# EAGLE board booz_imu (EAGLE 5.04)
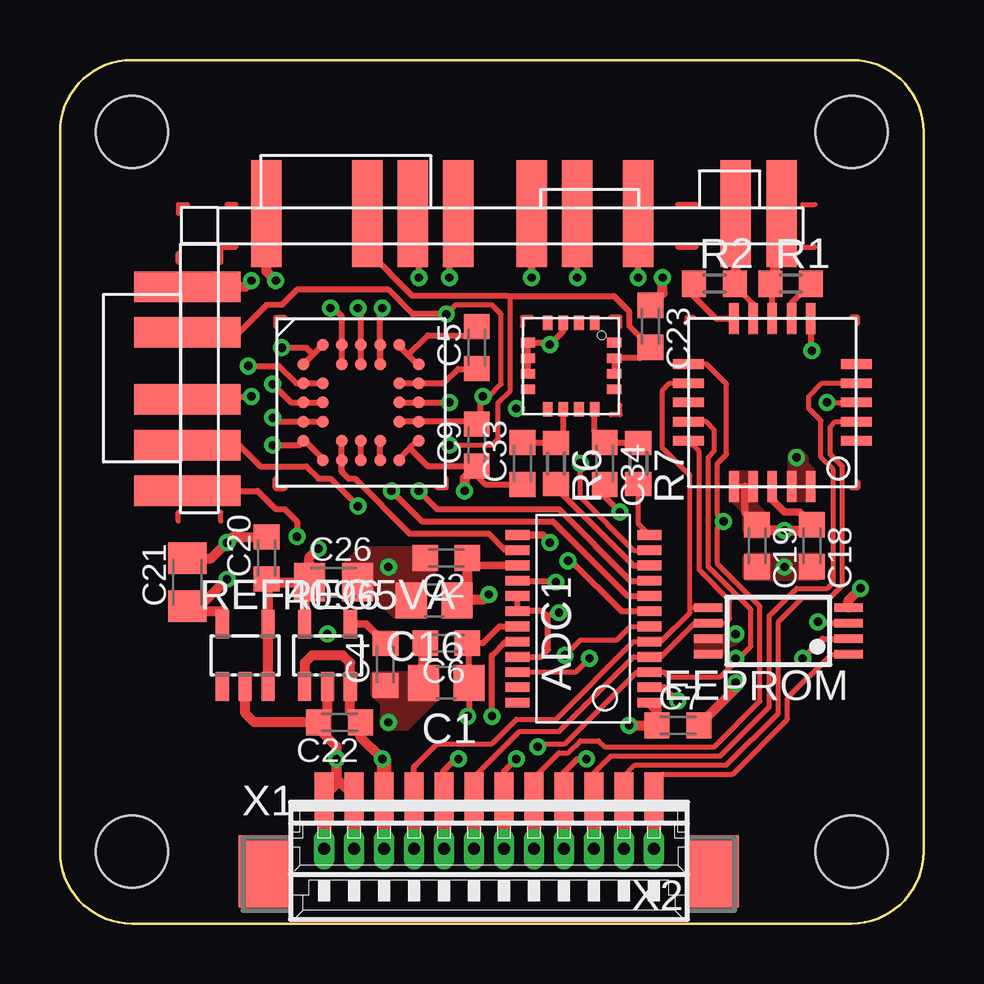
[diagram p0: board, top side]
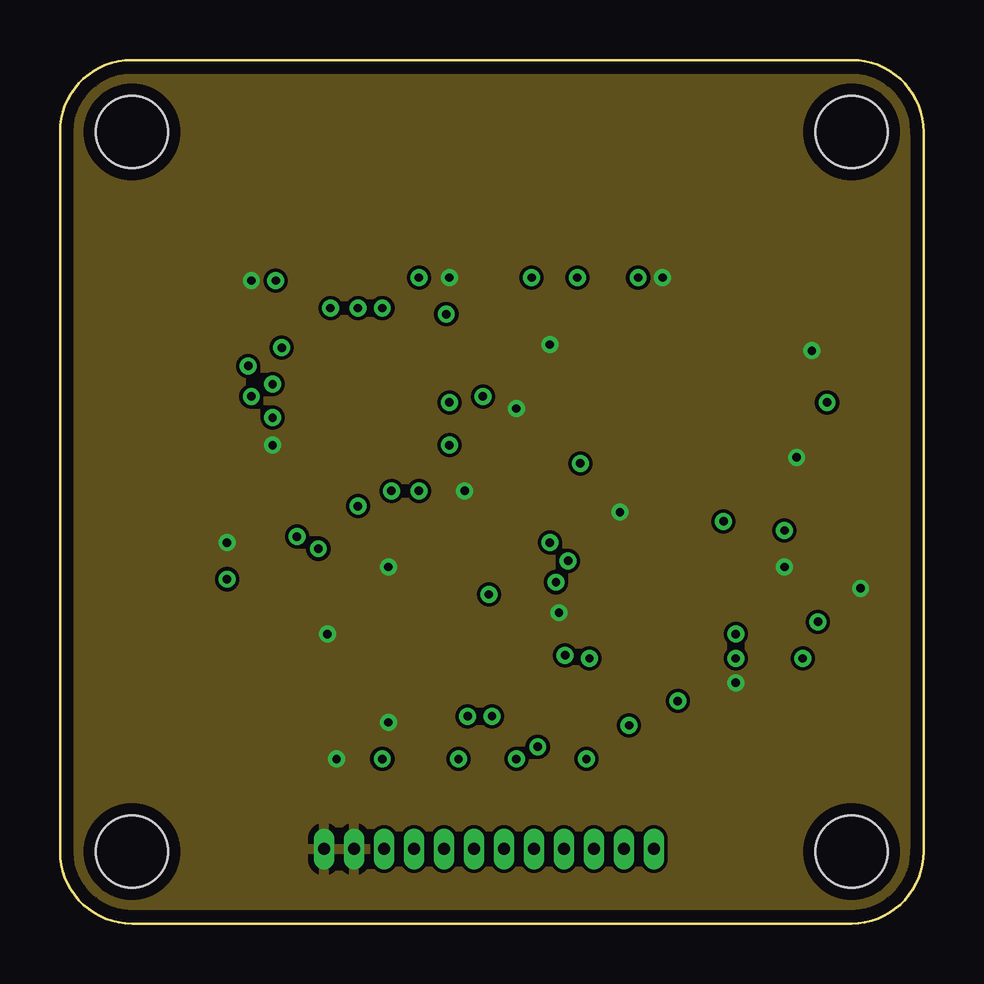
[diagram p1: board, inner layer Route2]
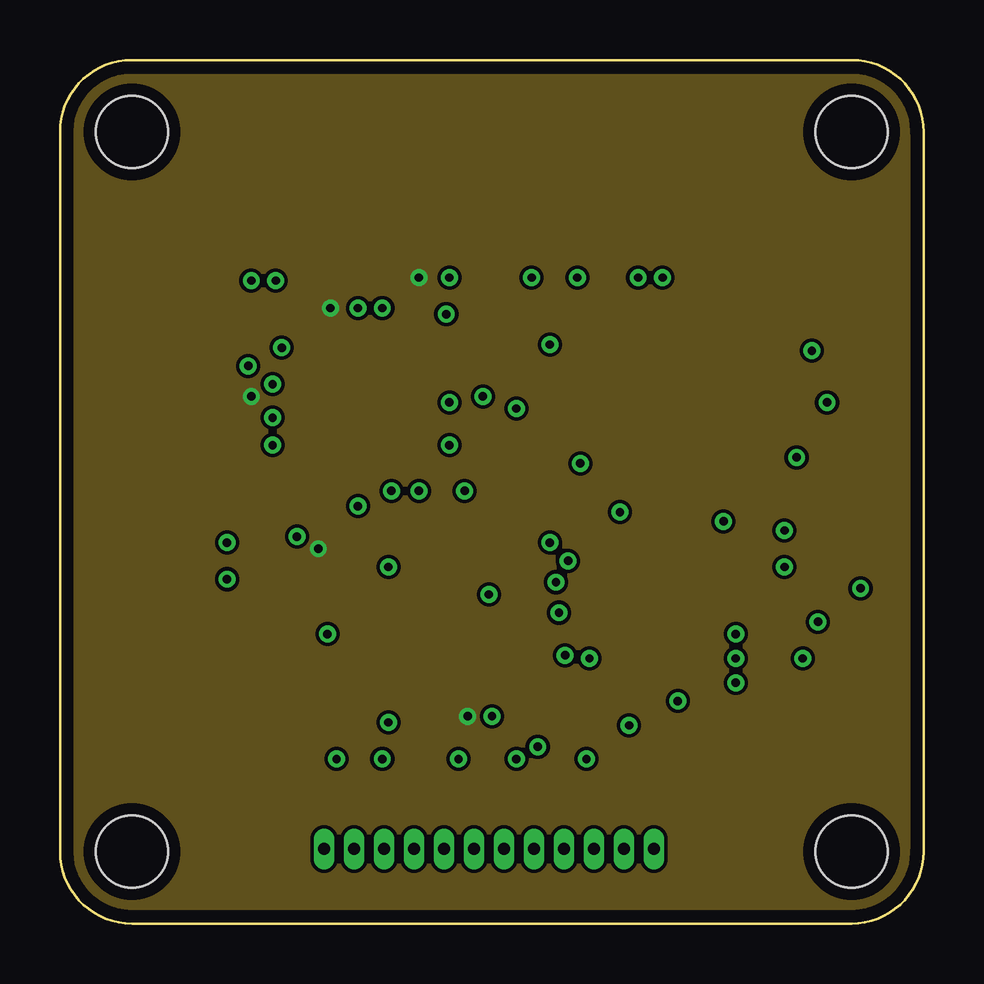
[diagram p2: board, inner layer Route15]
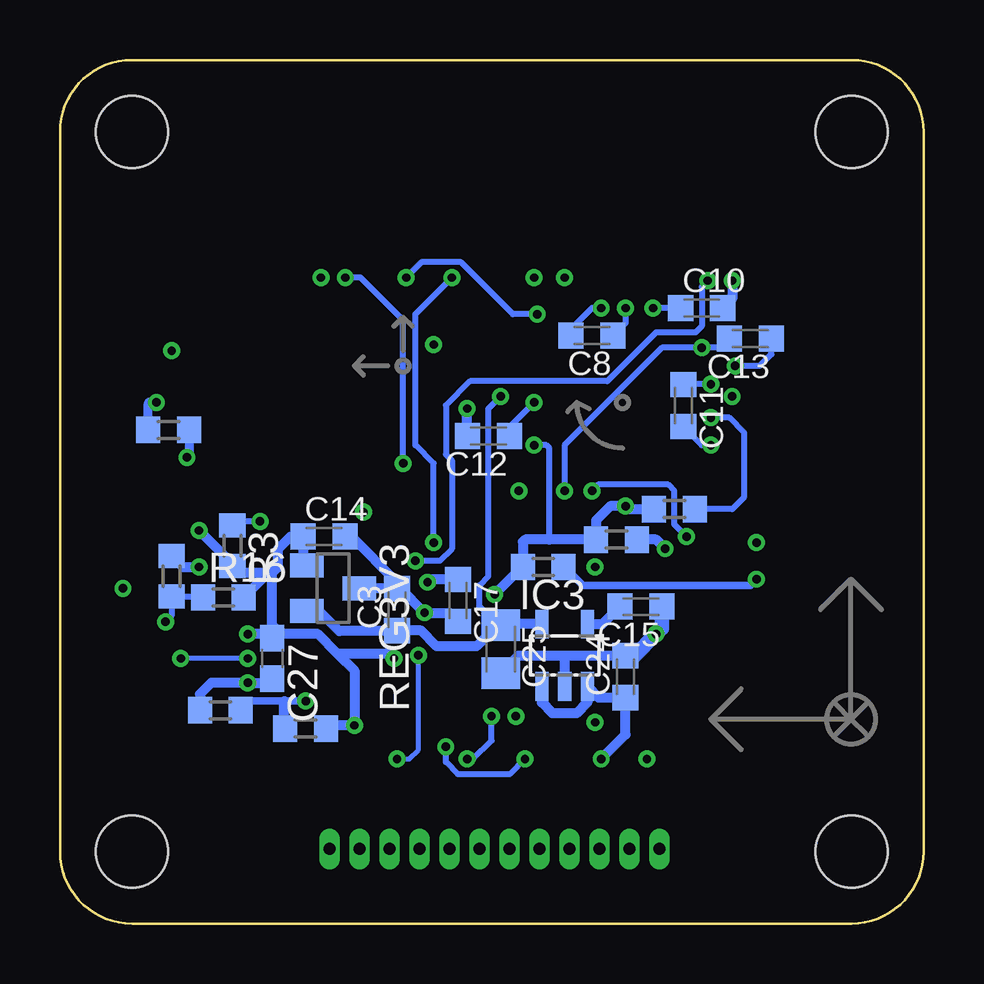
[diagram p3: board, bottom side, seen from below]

Size 36 x 36 mm. Coordinates in mm from the lower left corner, seen from the top.
Outline: 3,36 33,36 arc-90 36,33 36,3 arc-90 33,0 3,0 arc-90 0,3 0,33 arc-90 3,36
Copper layers (1*2+15*16): Top 0.035mm / dielectric 0.2mm / Route2 0.035mm / dielectric 1.5mm / Route15 0.035mm / dielectric 0.2mm / Bottom 0.035mm
Design rules "eurocircuits_verified_4l": minimum track width 0.15mm, minimum drill 0.35mm, track to track 0.15mm, track to pad 0.15mm, pad to pad 0.15mm, via to via 0.15mm, smd to smd 0.15mm, copper to edge 20mil, drill to drill 8mil, minimum pad ring 0.177mm, minimum via ring 0.177mm, stop-mask expansion 4mil, vias tented up to drill 14mil, thermal gap 10mil
Holes 3 mm at 3,33 33,33 33,3 3,3
tKeepout: area 0,30 to 6,36; area 30,30 to 36,36; area 0,0 to 6,6; area 30,0 to 36,6

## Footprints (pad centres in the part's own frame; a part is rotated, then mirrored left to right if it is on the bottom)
QSOP24 = smd 0.4 x 1: P$1 -3.493,-2.75; P$2 -2.857,-2.75; P$3 -2.223,-2.75; P$4 -1.587,-2.75; P$5 -0.953,-2.75; P$6 -0.318,-2.75; P$7 0.318,-2.75; P$8 0.953,-2.75; P$9 1.587,-2.75; P$10 2.223,-2.75; P$11 2.857,-2.75; P$12 3.493,-2.75; P$13 3.493,2.75; P$14 2.857,2.75; P$15 2.223,2.75; P$16 1.587,2.75; P$17 0.953,2.75; P$18 0.318,2.75; P$19 -0.318,2.75; P$20 -0.953,2.75; P$21 -1.587,2.75; P$22 -2.223,2.75; P$23 -2.857,2.75; P$24 -3.493,2.75
C0805 = smd 1.3 x 1.5: 1 -0.95,0; 2 0.95,0
C0603K = smd 1.05 x 1.08: 1 -0.875,0; 2 0.875,0
C0805K = smd 1.3 x 1.6: 1 -1,0; 2 1,0
C0603 = smd 1.1 x 1: 1 -0.85,0; 2 0.85,0
TSSOP8 = smd 0.35 x 1.2: 1 -0.975,-2.925; 2 -0.325,-2.925; 3 0.325,-2.925; 4 0.975,-2.925; 5 0.975,2.925; 6 0.325,2.925; 7 -0.325,2.925; 8 -0.975,2.925
BC-32 = smd 0.5 x 0.5: A2 -1.6,2.4; A3 -0.8,2.4; A4 0,2.4; A5 0.8,2.4; A6 1.6,2.4; B1 -2.4,1.6; B3 -0.8,1.6; B4 0,1.6; B5 0.8,1.6; B7 2.4,1.6; C1 -2.4,0.8; C2 -1.6,0.8; C6 1.6,0.8; C7 2.4,0.8; D1 -2.4,0; D2 -1.6,0; D6 1.6,0; D7 2.4,0; E1 -2.4,-0.8; E2 -1.6,-0.8; E6 1.6,-0.8; E7 2.4,-0.8; F1 -2.4,-1.6; F3 -0.8,-1.6; F4 0,-1.6; F5 0.8,-1.6; F7 2.4,-1.6; G2 -1.6,-2.4; G3 -0.8,-2.4; G4 0,-2.4; G5 0.8,-2.4; G6 1.6,-2.4
SOT23-5 = smd 0.55 x 1.2: 1 -0.95,-1.3; 2 0,-1.3; 3 0.95,-1.3; 4 0.95,1.3; 5 -0.95,1.3
QFN20 = smd 1.3 x 0.4: P$1 -3.5,1.6; P$2 -3.5,0.8; P$3 -3.5,0; P$4 -3.5,-0.8; P$5 -3.5,-1.6; P$11 3.5,-1.6; P$12 3.5,-0.8; P$13 3.5,0; P$14 3.5,0.8; P$15 3.5,1.6 | smd 0.4 x 1.3: P$6 -1.6,-3.5; P$7 -0.8,-3.5; P$8 0,-3.5; P$9 0.8,-3.5; P$10 1.6,-3.5; P$16 1.6,3.5; P$17 0.8,3.5; P$18 0,3.5; P$19 -0.8,3.5; P$20 -1.6,3.5
R0603 = smd 1 x 1.1: 1 -0.85,0; 2 0.85,0
SOT23-5L = smd 0.55 x 1.2: 1 -0.95,-1.3; 2 0,-1.3; 3 0.95,-1.3; 4 0.95,1.3; 5 -0.95,1.3
SOT23 = smd 1 x 1.4: 1 -0.95,-1.1; 2 0.95,-1.1; 3 0,1.1
LSCFP = smd 0.6 x 0.4: P$1 -1.8,0.975; P$2 -1.8,0.325; P$3 -1.8,-0.325; P$4 -1.8,-0.975; P$9 1.8,-0.975; P$10 1.8,-0.325; P$11 1.8,0.325; P$12 1.8,0.975 | smd 0.4 x 0.6: P$5 -0.975,-1.8; P$6 -0.325,-1.8; P$7 0.325,-1.8; P$8 0.975,-1.8; P$13 0.975,1.8; P$14 0.325,1.8; P$15 -0.325,1.8; P$16 -0.975,1.8
53261-12 = smd 0.8 x 2: 1 6.875,-2.5; 2 5.625,-2.5; 3 4.375,-2.5; 4 3.125,-2.5; 5 1.875,-2.5; 6 0.625,-2.5; 7 -0.625,-2.5; 8 -1.875,-2.5; 9 -3.125,-2.5; 10 -4.375,-2.5; 11 -5.625,-2.5; 12 -6.875,-2.5 | smd 2.1 x 3: S1 9.375,0.625; S2 -9.375,0.625
53047-12 = drill 0.5 pad 0.698 long: 1 6.875,0.45; 2 5.625,0.45; 3 4.375,0.45; 4 3.125,0.45; 5 1.875,0.45; 6 0.625,0.45; 7 -0.625,0.45; 8 -1.875,0.45; 9 -3.125,0.45; 10 -4.375,0.45; 11 -5.625,0.45; 12 -6.875,0.45
IMU_XZ = smd 1.27 x 4.445: GND 3.81,0.508; RATE -4.699,0.508; VDDA -0.889,0.508; VDDD 1.905,0.508; VREF -2.794,0.508
IMU_YZ_MAG = smd 1.27 x 4.445: ACCEL_H 3.81,0.508; ACCEL_V 8.255,0.508; GND 0.762,0.508; MAG_N 12.319,0.508; MAG_P 14.224,0.508; RATE_X -7.239,0.508; VDDA -1.143,0.508; VDDD 5.715,0.508; VREF -3.048,0.508

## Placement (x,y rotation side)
ADC1  MAX1168  [QSOP24]  21.82,12.7 90 top
C1  4.7uF  [C0805]  16.11,10.04 180 top
C2  100nF  [C0603K]  16.11,15.24 180 top
C3  100nF  [C0603K]  21.95,13.09 90 bottom
C4  10nF  [C0603K]  13.56,10.8 90 top
C5  22nF  [C0603K]  17.38,24.01 90 top
C6  100nF  [C0603K]  16.11,11.69 180 top
C7  100nF  [C0603K]  25.76,8.26 0 top
C8  22nF  [C0603K]  13.82,24.52 180 bottom
C9  100nF  [C0603K]  17.38,19.94 90 top
C10  100nF  [C0603K]  9.25,25.66 0 bottom
C11  100nF  [C0603K]  10.01,21.59 270 bottom
C12  47nF  [C0603K]  18.14,20.32 180 bottom
C13  22nF  [C0603K]  7.22,24.39 180 bottom
C14  100nF  [C0603K]  25,16.13 0 bottom
C15  10nF  [C0603K]  11.79,13.21 180 bottom
C16  4.7uF  [C0805]  15.6,13.47 180 top
C17  100nF  [C0603K]  19.41,13.47 270 bottom
C18  100nF  [C0603K]  31.34,15.75 270 top
C19  100nF  [C0603K]  29.06,15.75 270 top
C20  100nF  [C0603K]  8.61,15.24 90 top
C21  4.7uF/Low ESR  [C0805K]  5.31,14.23 90 top
C22  2.2uF/Low ESR  [C0603K]  11.66,8.39 180 top
C23  100nF  [C0603K]  24.61,24.9 270 top
C24  2.2uF/Low ESR  [C0603K]  12.42,10.29 90 bottom
C25  4.7uF/10V/Low ESR  [C0805K]  17.63,11.43 270 bottom
C26  4.7uF/10V/Low ESR  [C0805K]  11.41,14.23 0 top
C27  100nF  [C0603]  27.15,11.05 270 bottom
C33  100nF  [C0603K]  19.28,19.18 90 top
C34  100nF  [C0603K]  22.71,19.18 270 top
EEPROM  25LC040ST  [TSSOP8]  29.95,12.2 90 top
GYRO_Z  ADXR  [BC-32]  12.55,21.72 0 top
IC3  LP2992  [SOT23-5]  14.96,11.18 0 bottom
MAG  MS2100  [QFN20]  29.69,21.72 180 top
R1  43R  [R0603]  30.46,26.67 0 top
R2  43R  [R0603]  27.28,26.67 0 top
R3  10k  [R0603]  28.81,15.75 270 bottom
R4  39k/DNP  [R0603]  31.47,20.58 180 bottom
R5  10k/DNP  [R0603]  25.76,8.13 0 bottom
R6  12k  [R0603]  20.68,19.18 270 top
R7  12k  [R0603]  24.11,19.18 270 top
R8  0/DNP  [R0603]  12.8,16.01 180 bottom
R9  0/DNP  [R0603]  15.85,14.86 180 bottom
R10  0/DNP  [R0603]  10.39,17.28 0 bottom
R11  10k/DNP  [R0603]  29.31,8.89 0 bottom
R15  0/DNP  [R0603]  31.34,14.48 270 bottom
R16  4k7  [R0603]  29.19,13.59 0 bottom
REF4096  LM4132  [SOT23-5L]  7.72,11.18 0 top
REG3V3  LM3480  [SOT23]  24.61,13.97 270 bottom
REG5VA  LP2992  [SOT23-5]  11.15,11.18 0 top
U$2  ADXL320  [LSCFP]  21.31,23.24 270 top
X1  53261-12  [53261-12]  17.88,2.8 180 top
X2  53047-12  [53047-12]  17.88,3.56 180 top
XZ_BOARD  IMU_XZ_2  [IMU_XZ]  5.82,22.74 90 top
YZ_BOARD  IMU_YZ_MAG_2  [IMU_YZ_MAG]  15.85,29.09 0 top

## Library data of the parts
ADC1 MAG REF4096 REG3V3 XZ_BOARD YZ_BOARD = booz
C1-C27 C33 C34 R1-R11 R15 R16 = rcl
EEPROM = microchip
GYRO_Z U$2 = paparazzi
IC3 REG5VA = v-reg-micrel
X1 X2 = con-molex

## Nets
+3V3: ADC1.P$1 ADC1.P$22 C7.1 C14.1 C18.1 C19.1 C27.1 EEPROM.7 EEPROM.8 MAG.P$16 MAG.P$17 MAG.P$18 R3.2 R5.2 R16.2 REG3V3.1
+5V: C3.1 C9.2 C25.1 GYRO_Z.E6 GYRO_Z.E7 IC3.5 REG3V3.2 XZ_BOARD.VDDD YZ_BOARD.VDDD
+5VA: ADC1.P$19 C1.1 C6.1 C10.1 C20.1 C26.1 GYRO_Z.A3 GYRO_Z.B3 R8.1 REF4096.3 REF4096.4 REG5VA.5 XZ_BOARD.VDDA YZ_BOARD.VDDA
+6V5: C22.1 C24.1 IC3.1 IC3.3 REG5VA.1 REG5VA.3 X1.3 X2.3
ACCEL_X: ADC1.P$12 R7.2
ACCEL_X2: ADC1.P$13 YZ_BOARD.ACCEL_H
ACCEL_Y: ADC1.P$10 R6.2
ACCEL_Z: ADC1.P$11 YZ_BOARD.ACCEL_V
ADC_CS: ADC1.P$20 X1.7 X2.7
ADC_EOC: ADC1.P$6 X1.9 X2.9
EEPROM_CS: EEPROM.1 X1.12 X2.12
GND: ADC1.P$17 ADC1.P$18 ADC1.P$21 C1.2 C2.2 C3.2 C4.1 C6.2 C7.2 C9.1 C10.2 C11.2 C12.2 C14.2 C15.1 C16.2 C17.2 C18.2 C19.2 C20.2 C21.2 C22.2 C23.1 C24.2 C25.2 C26.2 C27.2 C33.1 C34.2 EEPROM.4 GYRO_Z.F1 GYRO_Z.F7 GYRO_Z.G2 GYRO_Z.G6 IC3.2 MAG.P$6 MAG.P$19 MAG.P$20 R4.1 R11.1 R15.1 REF4096.2 REG3V3.3 REG5VA.2 U$2.P$3 U$2.P$5 U$2.P$6 U$2.P$7 X1.1 X1.2 X2.1 X2.2 XZ_BOARD.GND YZ_BOARD.GND
MAG_CS: MAG.P$11 R3.1 X1.8 X2.8
MAG_DRDY: MAG.P$4 X1.10 X2.10
MAG_N: MAG.P$9 R2.2 YZ_BOARD.MAG_N
MAG_P: MAG.P$8 R1.1 YZ_BOARD.MAG_P
MAG_RESET: MAG.P$2 X1.11 X2.11
MISO: ADC1.P$3 EEPROM.2 MAG.P$14 X1.5 X2.5
MOSI: ADC1.P$5 EEPROM.5 MAG.P$12 X1.4 X2.4
N$1: ADC1.P$2 R5.1 R11.2
N$3: ADC1.P$16 C17.1
N$7: C5.2 GYRO_Z.A6 GYRO_Z.B7
N$8: C5.1 GYRO_Z.C6 GYRO_Z.C7
N$9: C8.2 GYRO_Z.A5 GYRO_Z.B5
N$10: C8.1 GYRO_Z.A4 GYRO_Z.B4
N$11: C13.1 GYRO_Z.C1 GYRO_Z.C2
N$12: C12.1 GYRO_Z.D6 GYRO_Z.D7
N$13: C11.1 GYRO_Z.D1 GYRO_Z.D2
N$15: MAG.P$10 R2.1
N$16: MAG.P$7 R1.2
N$18: MAG.P$3 R4.2
N$19: C15.2 IC3.4
N$20: C33.2 R6.1 U$2.P$10
N$23: C4.2 REG5VA.4
N$32: C34.1 R7.1 U$2.P$12
N$39: EEPROM.3 R15.2 R16.1
RATE_X: ADC1.P$8 XZ_BOARD.RATE
RATE_Y: ADC1.P$7 YZ_BOARD.RATE_X
RATE_Z: ADC1.P$9 C13.2 GYRO_Z.A2 GYRO_Z.B1
SCK: ADC1.P$4 EEPROM.6 MAG.P$15 X1.6 X2.6
ST1: GYRO_Z.F5 GYRO_Z.G5
ST2: GYRO_Z.F4 GYRO_Z.G4
TEMP: ADC1.P$14 GYRO_Z.F3 GYRO_Z.G3
V4096: C21.1 R9.1 REF4096.5
VRATIO_OR_2V5: GYRO_Z.E1 GYRO_Z.E2 R10.2
VREF: ADC1.P$15 C2.1 C16.1 C23.2 R8.2 R9.2 R10.1 U$2.P$14 U$2.P$15 XZ_BOARD.VREF YZ_BOARD.VREF

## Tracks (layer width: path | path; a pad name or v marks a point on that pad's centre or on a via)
+3V3  (via drill 0.35)
  Top 0.203: MAG.P$16 28.55,18.22 MAG.P$17 | ADC1.P$22 21.5,10.48 v22.07,11.05
  Top 0.305: MAG.P$18 29.69,17.66 30.2,17.15 30.82,17.15 C18.1 | 28.55,18.22 28.55,17.13 C19.1
  Top 0.406: ADC1.P$1 24.55,9.21 24.88,8.88 C7.1 v23.72,8.26 | C18.1 31.11,16.39 v30.2,16.39 29.3,16.39 C19.1
  Bottom 0.254: R5.2 24.61,8.13
  Bottom 0.406: C14.1 26.39,16.13 26.9,15.62 26.9,14.86 27.15,14.61 | C14.1 25.71,15.98 | 27.15,14.61 27.28,14.61 | REG3V3.1 25.87,15.08 C14.1 | v30.2,16.39 28.81,14.99 R3.2 28.51,14.61 27.28,14.61 | R16.2 27.32,14.61 27.28,14.61 | 27.15,12.45 C27.1 27.32,12.07 v28.17,12.07 | 27.15,12.45 27.15,14.61 | 27.15,12.45 26.77,12.07 25.25,12.07 24.42,11.24 | 24.42,11.24 23.72,10.55 v23.72,8.26 24.78,8.26 R5.2 | v22.07,11.05 22.26,11.24 24.42,11.24
  pour Top (no thermals): 26.52,11.94 26.52,11.18 27.53,11.18 28.42,11.94 28.42,12.2 28.17,12.32 27.66,11.94
  pour Top (no thermals): 28.04,18.8 28.93,18.8 28.93,17.66 28.93,17.53 29.31,17.15 29.31,16.13 28.81,16.13 28.55,16.39 28.55,17.15 28.04,17.66
+5V  (via drill 0.35)
  Top 0.203: v17.63,21.98 17.88,21.98 18.39,22.48 18.39,25.4 18.01,25.78 16.49,25.78 v16.11,25.4
  Top 0.254: 17.38,20.58 C9.2 17.38,20.7 | 17.38,20.7 17.38,20.83 17.29,20.92 GYRO_Z.E7 GYRO_Z.E6 | v21.57,26.93 YZ_BOARD.VDDD | 17.38,20.7 17.5,20.7 17.5,21.85 v17.63,21.98 | v16.11,25.4 14.71,25.4 13.69,26.42 9.88,26.42 9.25,25.78 8.61,25.78 7.47,24.64 XZ_BOARD.VDDD
  Bottom 0.254: v16.11,25.4 17.12,25.4 19.28,27.56 20.93,27.56 v21.57,26.93 | v17.63,21.98 18.14,21.47 18.14,14.48 18.52,14.1 18.52,13.21 17.74,12.43
  Bottom 0.406: IC3.5 17.58,12.48 C25.1 17.74,12.43 17.77,12.43 18.64,11.56 20.3,11.56 20.94,12.21 C3.1 22.44,12.21 22.45,12.2 24.36,12.2 25.19,13.02 REG3V3.2
+5VA  (via drill 0.35)
  Top 0.254: GYRO_Z.A3 GYRO_Z.B3 11.75,23.33 11.79,23.37 11.75,23.41 GYRO_Z.A3 | GYRO_Z.A3 11.75,25.31 11.41,25.66 v11.28,25.66 | v14.96,26.93 14.96,28.83 | 5.94,21.98 v7.98,21.98 | ADC1.P$19 18.33,12.39 17.63,11.69 C6.1 17.06,11.61 C1.1 17.06,8.7 v16.99,8.64
  Top 0.406: 8.67,14.31 C20.1 | 8.67,14.31 REF4096.4 REF4096.3 | 8.67,14.31 8.75,14.23 C26.1 | REG5VA.5 10.2,14.02 C26.1 | v10.77,15.62 10.39,15.24 10.39,14.24 C26.1 | 14.96,28.83 14.96,29.34 YZ_BOARD.VDDA | XZ_BOARD.VDDA 5.82,21.85 5.94,21.98
  Bottom 0.254: C10.1 v11.28,25.66
  Bottom 0.406: R8.1 11.15,16.01 v10.77,15.62
  pour Route15: 0.48,35.44 35.54,35.44 35.54,0.51 0.48,0.51
+6V5  (via drill 0.35)
  Top 0.406: REG5VA.1 10.2,10.87 10.52,11.18 11.79,11.18 12.1,10.87 REG5VA.3 12.1,8.82 C22.1 12.53,7.77 v13.44,6.86
  Top 0.61: v13.44,6.86 13.51,6.79 X1.3 X2.3
  Bottom 0.406: C24.1 12.42,9.31 | v13.44,6.86 12.42,7.88 C24.1 | IC3.1 15.91,9.21 15.47,8.77 14.45,8.77 14.01,9.21 IC3.3 13.55,9.42 C24.1
ACCEL_X
  Top 0.203: ADC1.P$12 24.11,16.66 R7.2
ACCEL_X2  (via drill 0.35)
  Top 0.305: v19.66,26.93 YZ_BOARD.ACCEL_H | ADC1.P$13 20.11,16.2 v20.42,15.88
  Bottom 0.254: v19.66,26.93 21.19,25.4 21.19,19.94 20.42,19.18 v20.42,15.88
ACCEL_Y
  Top 0.254: R6.2 20.68,18.16 20.93,17.91 23.92,14.93 ADC1.P$10
ACCEL_Z  (via drill 0.35)
  Top 0.203: ADC1.P$11 23.92,15.56 21.69,17.78 v21.69,19.18
  Top 0.254: v24.11,26.93 YZ_BOARD.ACCEL_V
  Bottom 0.254: v24.11,26.93 23.47,26.93 21.69,25.15 v21.69,19.18
ADC_CS  (via drill 0.35)
  Top 0.254: v19.03,6.86 18.52,6.35 X1.7 | ADC1.P$20 18.58,11.75 18.01,11.18 v18.01,8.64 18.01,8.51
  Top 0.61: X2.7 X1.7
  Bottom 0.254: v18.01,8.64 18.01,7.62 18.77,6.86 v19.03,6.86
ADC_EOC  (via drill 0.35)
  Top 0.203: v21.06,11.18 21.69,11.81 23.22,11.81 23.79,12.39 ADC1.P$6 | 21.01,3.18 21.01,5.8
  Top 0.254: 21.01,5.8 21.01,6.3 21.57,6.86 v21.95,6.86
  Top 0.61: 21.01,3 X2.9 21.01,3.18 X1.9
  Bottom 0.203: v21.95,6.86 21.44,6.86 21.06,7.24 v21.06,11.18
EEPROM_CS
  Top 0.203: 24.87,5.97 25.12,6.23 28.04,6.23 30.33,8.51 30.33,9.4 32.15,11.22 EEPROM.1
  Top 0.406: 24.87,5.97 24.87,5.41 X1.12
  Top 0.61: X2.12 X1.12
GND  (via drill 0.35)
  Top 0.203: 20.51,24.22 v20.42,24.13
  Top 0.254: 14.09,19.32 14.07,19.31 | GYRO_Z.G6 14.09,19.32 | 14.09,19.32 14.58,19.82 | C34.2 22.71,17.78 v23.34,17.15 | 10.15,20.18 10.14,20.2 | 10.15,20.18 GYRO_Z.F1 9.97,19.94 v8.87,19.94 | GYRO_Z.G2 10.95,19.38 10.15,20.18 | v16.23,26.93 16.23,28.71 | 14.58,19.82 14.89,20.12 GYRO_Z.F7 | C20.2 8.6,16.12 | ADC1.P$17 ADC1.P$18 20.1,13.02 20.34,12.78 | ADC1.P$21 20.04,11.12 20.34,11.42 20.34,12.78 | U$2.P$7 U$2.P$6 U$2.P$5 20.51,24.22 20.99,24.7 U$2.P$3 | C33.1 17.74,18.31 17.23,18.81 17.23,18.93 C9.1 15.33,19.07 14.58,19.82 | 20.34,12.78 20.52,12.96 v20.8,12.96 | MAG.P$6 31.29,23.93 v31.34,23.88
  Top 0.406: 7.72,9.78 REF4096.2 7.72,8.77 8.1,8.39 C22.2 | v11.53,6.86 11.53,7.37 10.78,8.12 C22.2 | XZ_BOARD.GND 7.72,26.55 v7.98,26.8 | C21.2 6.31,15.23 v6.96,15.88 7.2,16.12 C20.2 | v11.53,6.86 11.53,5.82 X1.1 | X1.2 11.53,6.02 v11.53,6.86 | REG5VA.2 11.15,8.75 C22.2 | C6.2 15.16,11.61 C1.2 | C4.1 13.68,9.92 | C23.1 25.12,26.28 v25.12,26.93 | v33.38,13.97 32.87,13.47 EEPROM.4 | C7.2 28.17,9.8 v28.17,10.04 | v16.87,18.04 16.87,18.56 C9.1 | 16.23,28.71 16.61,29.09 YZ_BOARD.GND
  Top 0.61: X2.1 11.03,3.13 11.03,5.21 | X2.2 X1.2 12.3,5.34
  Bottom 0.254: C11.2 10.01,20.7 9.25,19.94 v8.87,19.94
  Bottom 0.381: v30.71,19.44 30.62,19.52 R4.1
  Bottom 0.406: R11.1 30.16,9.57 29.69,10.04 v28.17,10.04 27.32,10.04 C27.2 | C10.2 7.98,26.05 v7.98,26.8 | C3.2 21.95,14.23 23.85,16.13 C14.2 | C3.2 21.83,13.85 | v19.03,21.47 19.03,20.34 C12.2 | C17.2 19.77,12.96 v20.8,12.96 21.81,13.96 C3.2 | C25.2 16.9,11.17 14.96,11.17 | C24.2 14.96,11.17 | 14.96,10.29 IC3.2 14.96,11.17 | REG3V3.3 C3.2 | R15.1 30.88,14.86 v30.2,14.86
  Bottom 0.61: 12.41,11.18 C24.2 12.06,11.17 v11.15,12.07 10.91,12.31 C15.1
  other vias: 13.69,14.86 13.69,8.39
  pour Route2: 0.36,35.44 35.41,35.44 35.41,0.38 0.36,0.38
  pour Top (no thermals): 13.56,8.13 13.44,8.26 13.44,9.15 13.06,9.53 13.06,10.42 15.72,10.42 15.72,9.4 14.45,8.13
  pour Top (no thermals): 15.6,15.62 12.55,15.62 11.91,14.99 11.91,13.72 12.04,13.59 13.18,13.59 13.95,12.83 15.22,12.83 15.22,14.35 15.6,14.74
  pour Top (no thermals): 28.68,15.37 31.6,15.37 31.73,15.24 31.73,14.48 31.6,14.35 28.68,14.35 28.55,14.48 28.55,15.24
  pour Top (no thermals): 30.46,17.78 30.46,19.56 30.58,19.69 30.84,19.69 31.09,19.44 31.09,19.18 31.34,18.93 31.34,17.78 31.22,17.66 30.58,17.66
MAG_CS  (via drill 0.35)
  Top 0.203: 19.76,5.44 19.76,6.07 20.8,7.12 21.19,7.12 21.69,7.62 22.45,7.62 22.71,7.37 27.28,7.37 29.19,9.27 29.19,9.91 29.19,13.21 27.41,14.99 27.41,16.51 v27.66,16.77 27.41,17.02 27.41,19.18 27.79,19.56 27.79,22.48 26.95,23.32 MAG.P$11
  Top 0.61: X2.8 X1.8 19.76,5.44
  Bottom 0.254: v27.66,16.77 28.64,16.77 R3.1
MAG_DRDY
  Top 0.203: MAG.P$4 31.76,22.52 31.22,21.98 31.22,21.47 31.73,20.96 31.73,19.44 32.23,18.93 32.23,14.23 31.98,13.97 30.71,13.97 29.57,12.83 29.57,9.66 29.57,9.02 27.53,6.99 22.96,6.99 22.26,6.28 22.26,3.36
  Top 0.61: X1.10 22.26,3.36 X2.10
MAG_N
  Top 0.254: MAG.P$9 28.89,25.82 28.04,26.67 R2.2
  Top 0.406: R2.2 28.17,26.71 YZ_BOARD.MAG_N 28.26,29.51 28.26,29
MAG_P
  Top 0.254: MAG.P$8 29.69,26.59 R1.1
  Top 0.406: R1.1 29.82,26.89 29.82,28.83 29.99,29 29.99,29.51 YZ_BOARD.MAG_P
MAG_RESET
  Top 0.203: MAG.P$2 32.32,20.92 32.11,20.7 32.11,19.56 32.61,19.05 32.61,14.1 32.11,13.59 30.96,13.59 29.95,12.58 29.95,10.04 29.95,8.77 27.79,6.61 23.98,6.61 23.51,6.14 23.51,5.38
  Top 0.254: 23.51,3.6 23.51,5.38
  Top 0.61: X1.11 23.51,3.6 X2.11
MISO  (via drill 0.35)
  Top 0.203: MAG.P$14 26.94,20.92 27.28,20.58 27.28,19.69 27.03,19.44 27.03,14.86 28.81,13.09 28.81,11.56 28.3,11.05 v28.17,11.05 28.17,10.93 27.53,10.29 25.38,10.29 25.19,10.48 ADC1.P$3 24.04,10.48 21.06,7.5 20.04,7.5 v19.92,7.37
  Top 0.254: X1.5 arc-90 15.98,4.69 15.98,6.35 16.49,6.86 v16.61,6.86 | EEPROM.2 31.78,11.87 v30.96,11.05
  Top 0.61: X2.5 16.01,4.66 15.98,4.69
  Bottom 0.203: v28.17,11.05 v30.96,11.05
  Bottom 0.254: v16.61,6.86 17.25,6.23 19.41,6.23 19.92,6.73 v19.92,7.37
MOSI
  Top 0.203: MAG.P$12 25.41,22.52 25.12,22.23 25.12,19.82 26.27,18.67 26.27,13.17 | 14.83,6.61 15.72,7.5 18.01,7.5 19.03,8.51 20.68,8.51 23.92,11.75 ADC1.P$5 25.06,11.75 26.27,12.96 26.27,13.17 | 26.27,13.17 EEPROM.5
  Top 0.254: 14.83,6.61 14.76,6.53 X1.4
  Top 0.61: X2.4 X1.4
N$1  (via drill 0.35)
  Top 0.254: ADC1.P$2 25.19,9.85 v25.76,9.27
  Bottom 0.305: v25.76,9.27 26.65,9.27 28.08,9.27 R11.2
  Bottom 0.406: R5.1 26.65,8.17 26.65,9.27
N$2
  Top 0.203: 26.52,29.98 25.76,29.98
N$3  (via drill 0.35)
  Top 0.254: ADC1.P$16 20.61,14.29 v20.68,14.23
  Bottom 0.406: C17.1 19.42,14.35 20.55,14.35 v20.68,14.23
N$4
  Top 0.203: 25.76,28.2 26.52,28.2
N$5
  Top 0.203: 7.34,29.98 6.96,29.98
N$6
  Top 0.203: 30.96,29.98 31.47,29.98
N$7
  Top 0.254: 14.09,24.12 14.07,24.13 | 14.09,24.12 GYRO_Z.A6 | GYRO_Z.B7 14.89,23.32 14.52,23.69 | 14.52,23.69 14.09,24.12 | 14.52,23.69 15.34,24.52 17.01,24.52 C5.2
N$8
  Top 0.254: GYRO_Z.C6 14.11,22.52 | 14.11,22.52 GYRO_Z.C7 16.02,22.52 16.61,23.12 17.38,23.12 C5.1 | 14.11,22.52 14.07,22.48
N$9  (via drill 0.35)
  Top 0.254: GYRO_Z.A5 GYRO_Z.B5 13.35,23.28 | GYRO_Z.A5 13.35,25.57 v13.44,25.66 | GYRO_Z.A5 13.35,23.28 | 13.35,23.28 13.31,23.24
  Bottom 0.254: v13.44,25.66 13.82,25.66 14.69,24.78 C8.2
N$10  (via drill 0.35)
  Top 0.254: GYRO_Z.A4 12.55,24.13 | GYRO_Z.B4 GYRO_Z.A4 | GYRO_Z.A4 12.55,25.53 v12.42,25.66
  Bottom 0.254: C8.1 12.42,25.04 v12.42,25.66
N$11  (via drill 0.35)
  Top 0.254: GYRO_Z.C2 GYRO_Z.C1 9.84,22.52 9.12,23.24 v7.85,23.24
  Bottom 0.254: v7.85,23.24 6.83,23.24 6.34,23.74 C13.1
N$12  (via drill 0.35)
  Top 0.254: GYRO_Z.D6 GYRO_Z.D7 | GYRO_Z.D7 v16.23,21.72 | GYRO_Z.D6 14.07,21.72 | GYRO_Z.D6 GYRO_Z.D7
  Bottom 0.254: 17.25,20.32 C12.1 17.26,20.69 v16.23,21.72
N$13  (via drill 0.35)
  Top 0.254: GYRO_Z.D1 10.14,21.72 | GYRO_Z.D1 GYRO_Z.D2 | v8.87,22.48 9.63,21.72 GYRO_Z.D1
  Bottom 0.254: v8.87,22.48 10.02,22.48 C11.1
N$14
  Top 0.203: 4.93,29.59 4.93,29.98 5.31,29.98
N$15
  Top 0.254: MAG.P$10 27.34,25.22 26.43,26.13 R2.1
N$16
  Top 0.254: MAG.P$7 30.49,25.86 R1.2
N$17
  Top 0.203: 6.71,27.56 6.71,28.2 7.34,28.2
N$18  (via drill 0.35)
  Top 0.203: v31.98,21.72 MAG.P$3
  Bottom 0.381: v31.98,21.72 32.28,21.72 32.32,21.68 R4.2
N$19
  Bottom 0.406: C15.2 13.39,12.48 IC3.4
N$20
  Top 0.254: U$2.P$10 20.99,20.03 R6.1 19.31,20.03 C33.2
N$21
  Top 0.203: 4.93,27.56 4.93,27.94
N$22
  Top 0.203: 4.93,16.77 4.93,17.15
N$23
  Top 0.254: C4.2 13.56,11.69
  Top 0.305: REG5VA.4 12.76,12.48 C4.2
N$24
  Top 0.203: 6.71,16.77 6.71,17.15
N$25
  Top 0.203: 30.96,28.2 31.47,28.2
N$26
  Top 0.203: 26.39,25.28 26.14,25.28 26.14,25.02
N$27
  Top 0.203: 33,18.16 33.25,18.16 33.25,18.42
N$28
  Top 0.203: 33,25.28 33.25,25.28 33.25,25.02
N$29
  Top 0.203: 22.96,21.21 23.34,21.21 23.34,21.59
N$30
  Top 0.203: 22.96,25.28 23.34,25.28 23.34,24.9
N$31
  Top 0.203: 19.66,25.28 19.28,25.28 19.28,24.9
N$32
  Top 0.254: U$2.P$12 22.29,20.48 C34.1 22.73,20.03 R7.1
N$33
  Top 0.203: 8.99,24.9 8.99,25.28 9.37,25.28
N$34
  Top 0.254: 8.99,18.55 8.99,18.16 9.37,18.16
N$35
  Top 0.203: 16.11,18.55 16.11,18.16 15.72,18.16
N$39  (via drill 0.35)
  Top 0.254: EEPROM.3 31.66,12.52 v31.6,12.58
  Bottom 0.254: R16.1 30.08,13.63 R15.2 31.34,12.83 v31.6,12.58
RATE_X  (via drill 0.35)
  Top 0.254: ADC1.P$8 23.66,13.66 20.55,16.77 15.09,16.77 v13.82,18.04 | XZ_BOARD.RATE 8.23,18.04 8.99,17.28 9.37,17.28 9.88,16.77 v9.88,16.13
  Bottom 0.254: v13.82,18.04 13.56,18.29 10.64,18.29 10.39,18.04 10.39,16.64 v9.88,16.13
RATE_Y  (via drill 0.35)
  Top 0.254: ADC1.P$7 23.41,13.02 21.31,15.12 v21.19,15.12
  Top 0.406: v8.99,26.8 8.61,27.18 YZ_BOARD.RATE_X
  Bottom 0.254: v21.19,15.12 20.17,15.12 19.66,15.62 19.66,19.31 19.92,19.56 19.92,21.59 18.9,22.61 13.18,22.61 11.15,24.64 9.5,24.64 9.25,24.9 9.25,26.55 v8.99,26.8
RATE_Z  (via drill 0.35)
  Top 0.254: 10.55,23.72 GYRO_Z.B1 10.14,23.31 10.14,23.24 | 10.55,23.72 GYRO_Z.A2 | v14.96,18.04 15.72,17.28 20.8,17.28 23.79,14.29 ADC1.P$9 | v9.25,24.01 10.26,24.01 10.55,23.72
  Bottom 0.254: C13.2 8.1,24.39 8.48,24.01 v9.25,24.01 10.9,24.01 14.96,19.94 v14.96,18.04
SCK
  Top 0.203: 17.25,5.59 17.25,6.1 19.15,8.01 20.8,8.01 23.92,11.12 ADC1.P$4 25.06,11.12 26.46,12.52 EEPROM.6 27.73,12.52 27.92,12.7 27.92,13.47 26.65,14.74 26.65,19.67 MAG.P$15 26.27,20.05 | X1.6 17.26,5.6
  Top 0.254: 17.26,5.6 17.25,5.59
  Top 0.61: X2.6 X1.6
ST1
  Top 0.254: 13.32,19.32 13.31,19.31 | GYRO_Z.G5 13.32,19.32 | GYRO_Z.F5 13.35,19.35 13.32,19.32
ST2
  Top 0.254: 12.55,19.31 GYRO_Z.G4 GYRO_Z.F4
TEMP
  Top 0.203: 18.58,15.56 ADC1.P$14
  Top 0.254: GYRO_Z.G3 GYRO_Z.F3 11.75,20.16 | GYRO_Z.G3 11.75,20.16 | 11.75,20.16 11.79,20.2 | GYRO_Z.G3 11.75,18.89 | 18.58,15.56 17.88,16.26 14.58,16.26 12.3,18.55 12.04,18.55 11.75,18.84 GYRO_Z.G3
V4096  (via drill 0.35)
  Top 0.203: C21.1 5.31,13.34 5.67,13.34
  Top 0.406: C21.1 5.31,13.21 5.49,13.03 6.77,13.03 REF4096.5 | 5.67,13.34 5.94,13.34 v6.96,14.35
  Bottom 0.305: 14.96,14.86 14.2,14.1 7.22,14.1 v6.96,14.35
  Bottom 0.406: v6.96,14.35 7.09,14.23 | 14.96,14.86 R9.1
VRATIO_OR_2V5  (via drill 0.35)
  Top 0.254: GYRO_Z.E2 GYRO_Z.E1 9.03,20.92 v8.87,21.09
  Bottom 0.254: v8.87,21.09 8.1,21.09 7.47,20.45 7.47,17.78 7.98,17.28 R10.2
VREF  (via drill 0.35)
  Top 0.203: 18.64,26.17 18.77,26.17 18.77,22.23 18.26,21.72 18.26,20.2 18.01,19.94 v16.23,19.94
  Top 0.254: U$2.P$14 23.11,23.48 23.09,23.5 23.11,23.52 U$2.P$15 24.16,23.57 C23.2 23.72,24.91 23.72,25.53 23.09,26.17 18.64,26.17 14.71,26.17 12.8,28.07 YZ_BOARD.VREF | XZ_BOARD.VREF 7.47,19.94 8.36,19.05 10.26,19.05 10.77,18.55 11.28,18.55 v12.42,17.4
  Top 0.305: ADC1.P$15 17.3,14.93 C2.1
  Top 0.406: 16.98,13.49 C2.1 | 16.98,13.49 17.65,13.49 v17.88,13.72 | 16.98,13.49 16.57,13.49 C16.1
  Bottom 0.254: v16.23,19.94 15.72,19.94 15.6,19.82 15.6,16.01
  Bottom 0.406: R10.1 12.3,17.28 v12.42,17.4 13.06,17.4 13.65,16.81 R8.2 15.6,16.01 16.61,16.01 16.7,15.92 R9.2 16.7,14.65 16.95,14.65 v17.88,13.72

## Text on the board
tDocu: Quadrotor IMU v1.02 | 2009/05
bDocu: Quadrotor IMU v1.02 | 2009/05 | Ay | r | Ax | Y | Z | X | GND | GND | +6V5 | MOSI | MISO | SCK | ADC_CS | MAG_CS | ADC_EOC | MAG_DRDY | MAG_RESET | EE_CS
